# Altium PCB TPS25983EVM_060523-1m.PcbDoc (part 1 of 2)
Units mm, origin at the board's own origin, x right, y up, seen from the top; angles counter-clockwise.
Board outline 76.2 x 78.74 mm, 4 copper layers (L1-Top Layer, L2-GND1, L3-PWR/SIG, L4-Bottom Layer), stack 1.554 mm thick; 100 components, 38 nets, 213 pads, 280 vias.
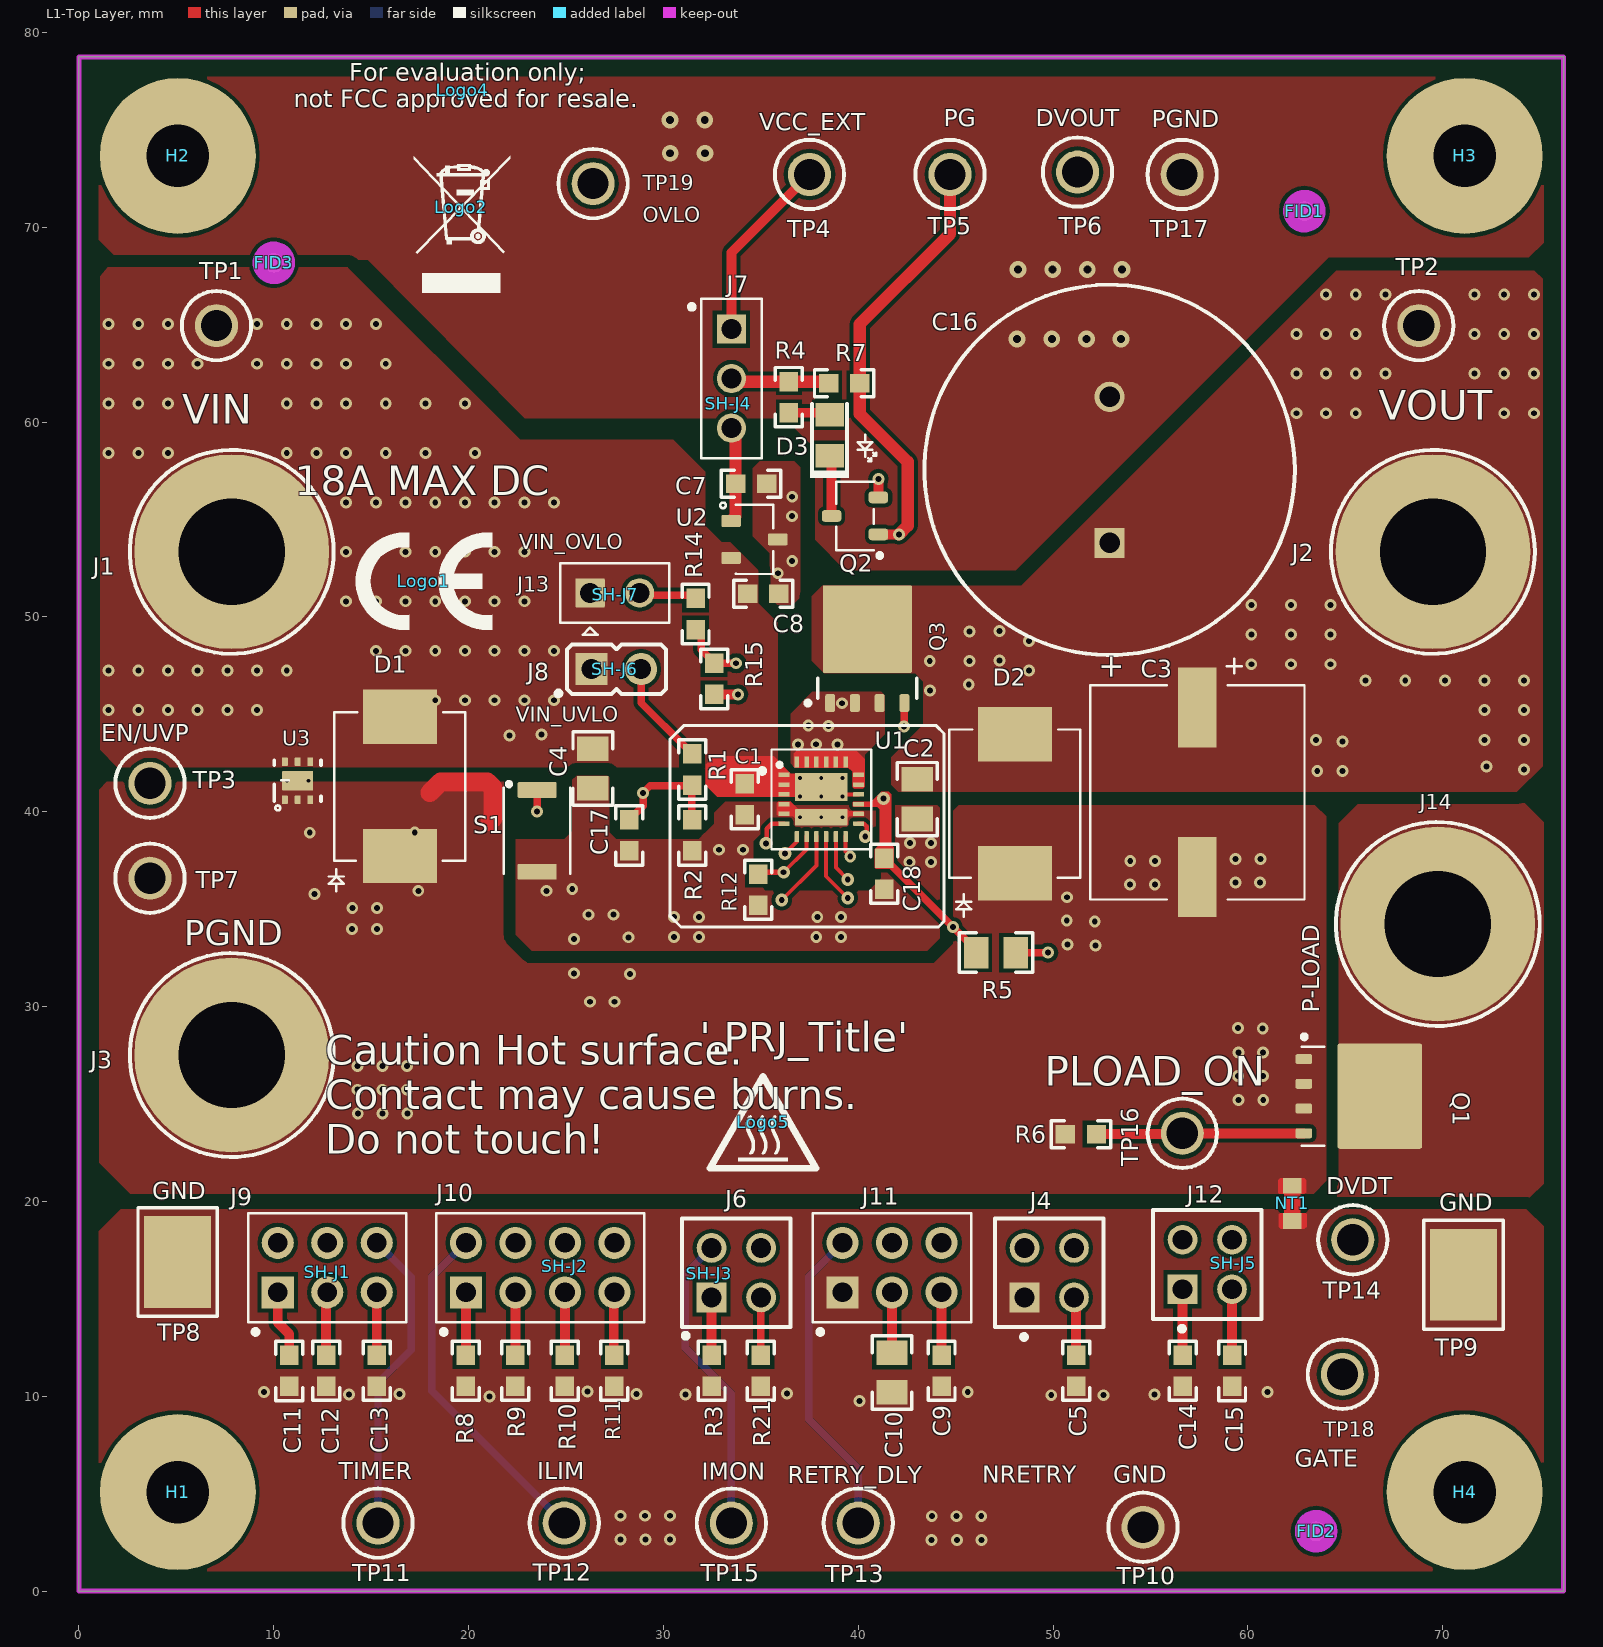
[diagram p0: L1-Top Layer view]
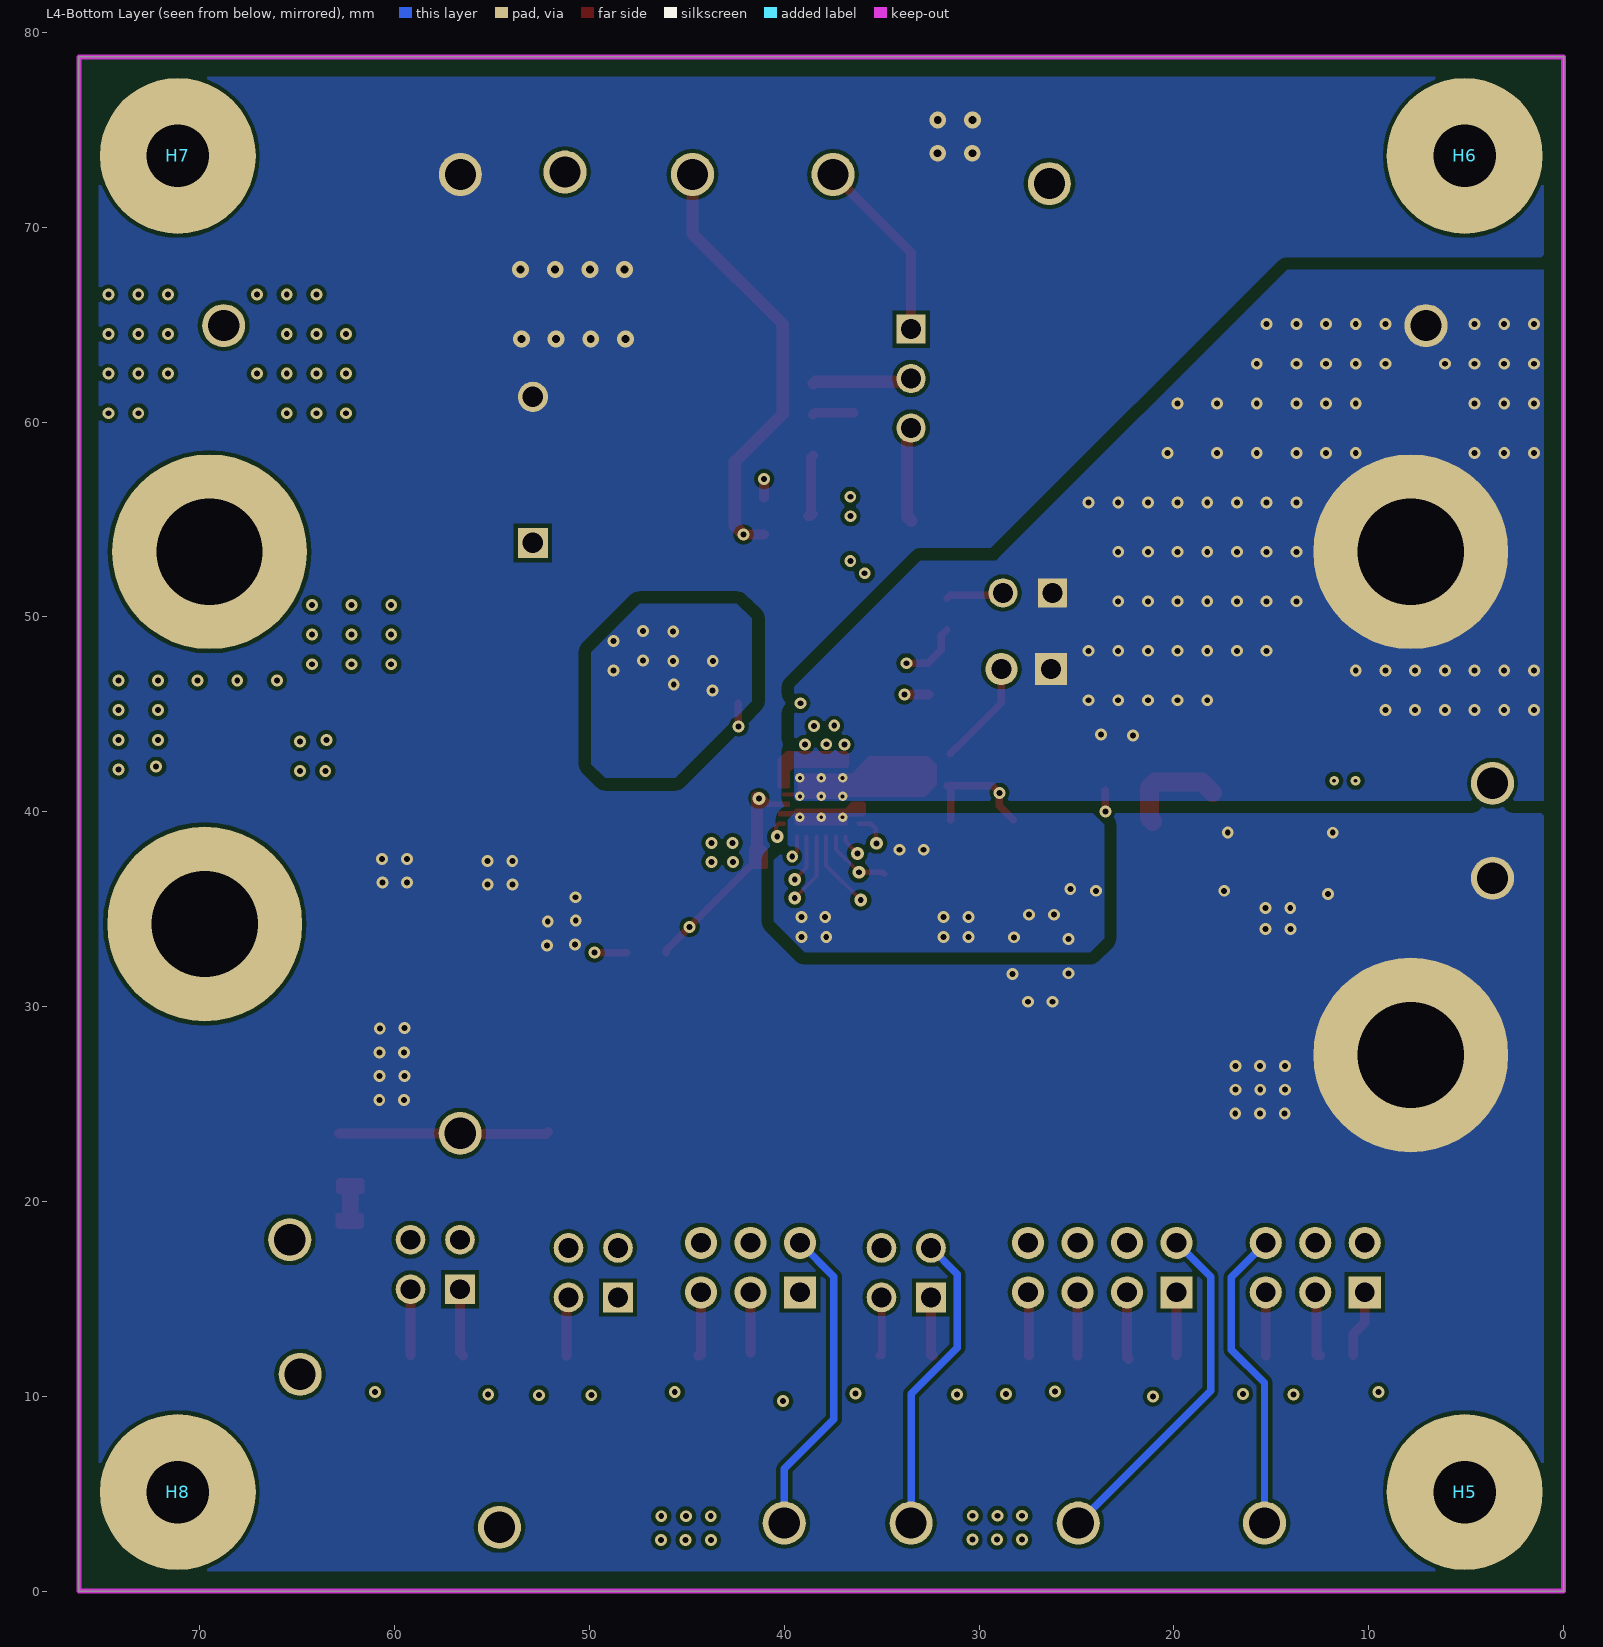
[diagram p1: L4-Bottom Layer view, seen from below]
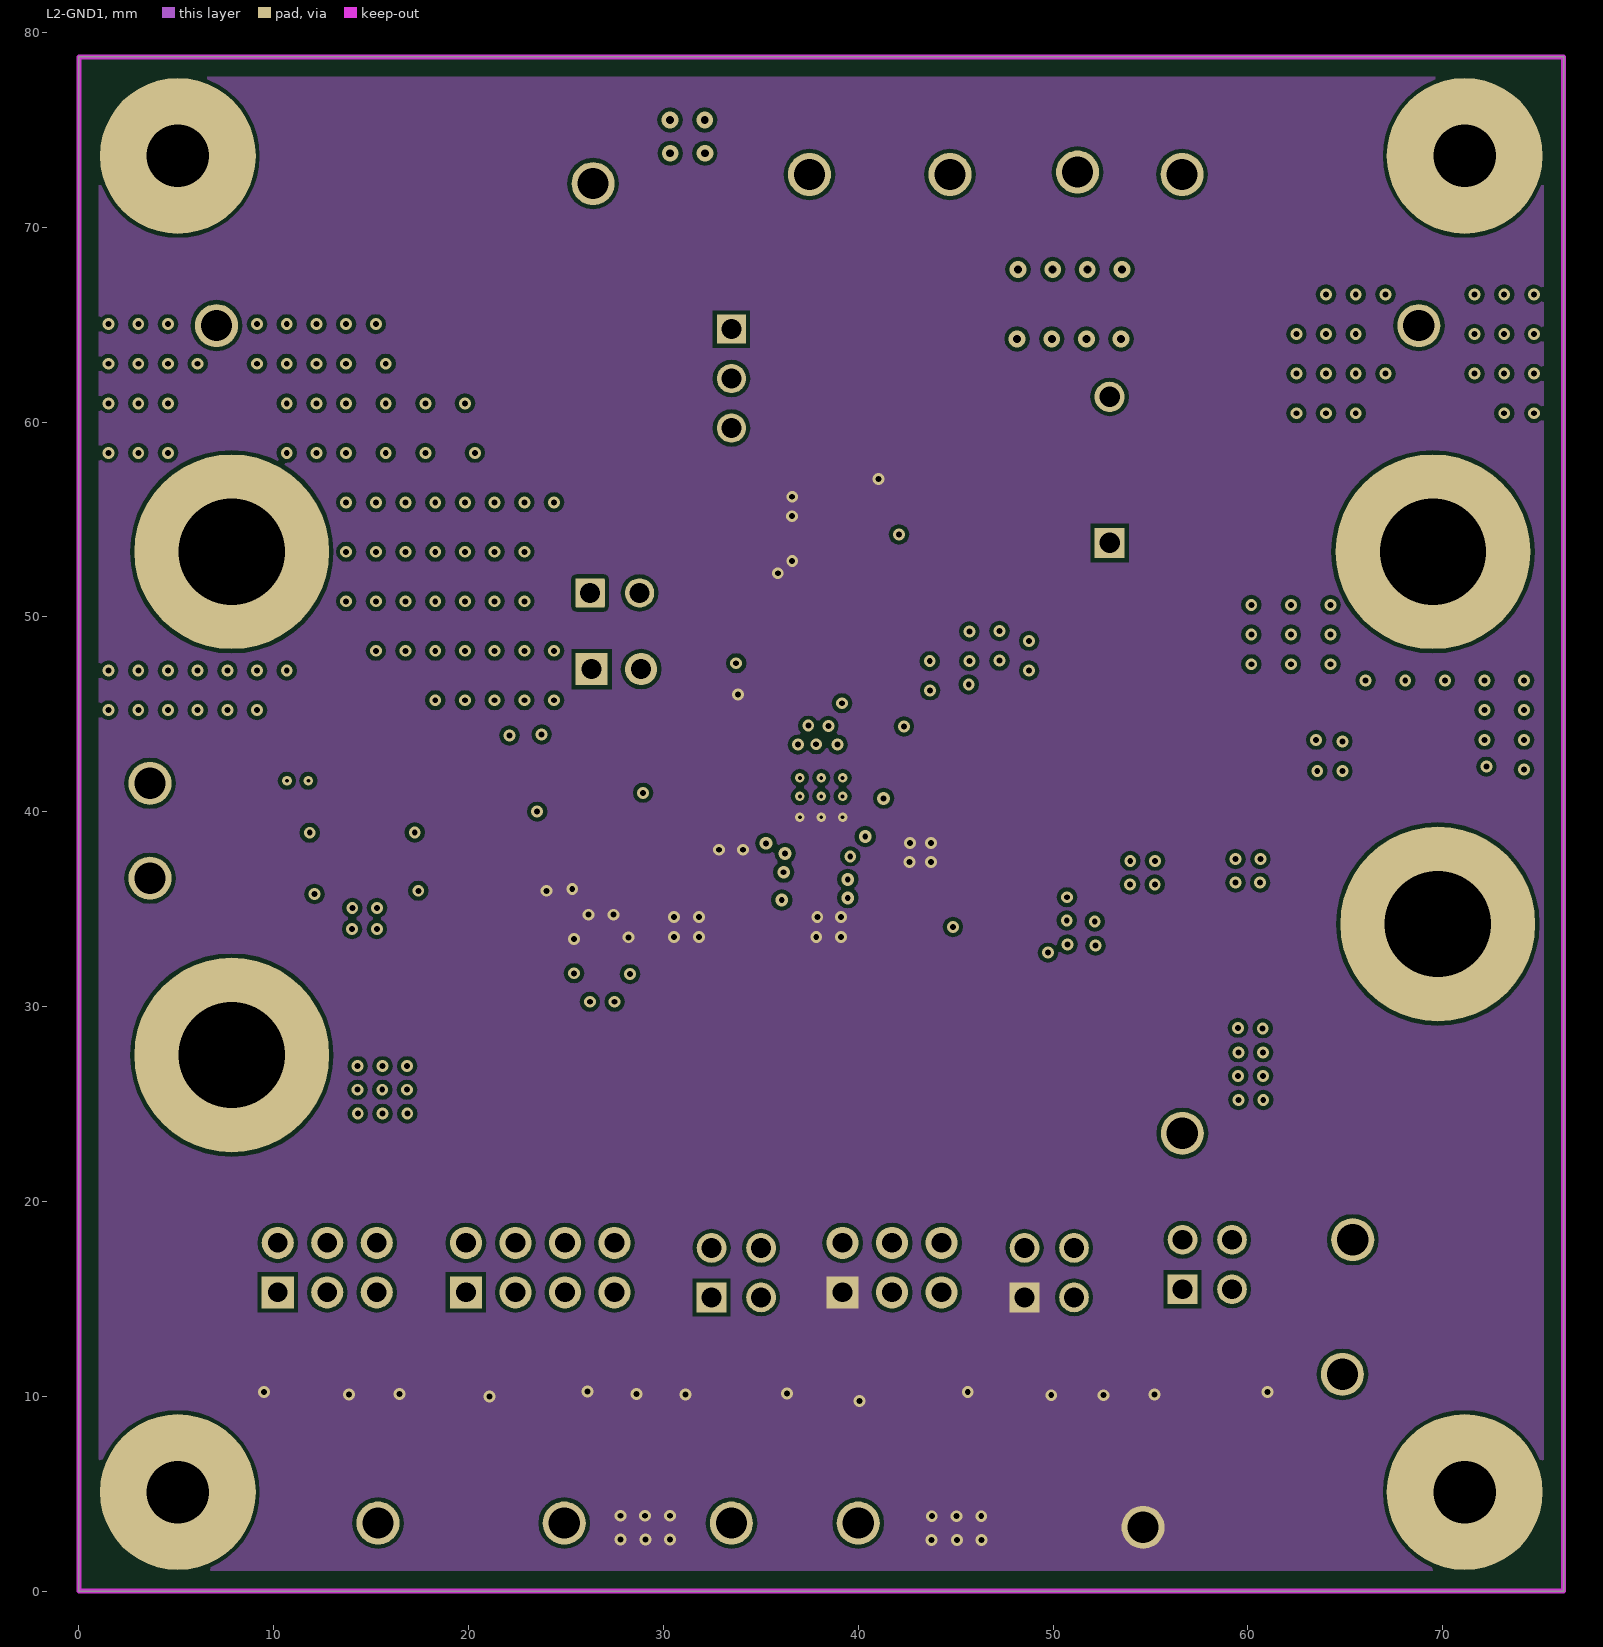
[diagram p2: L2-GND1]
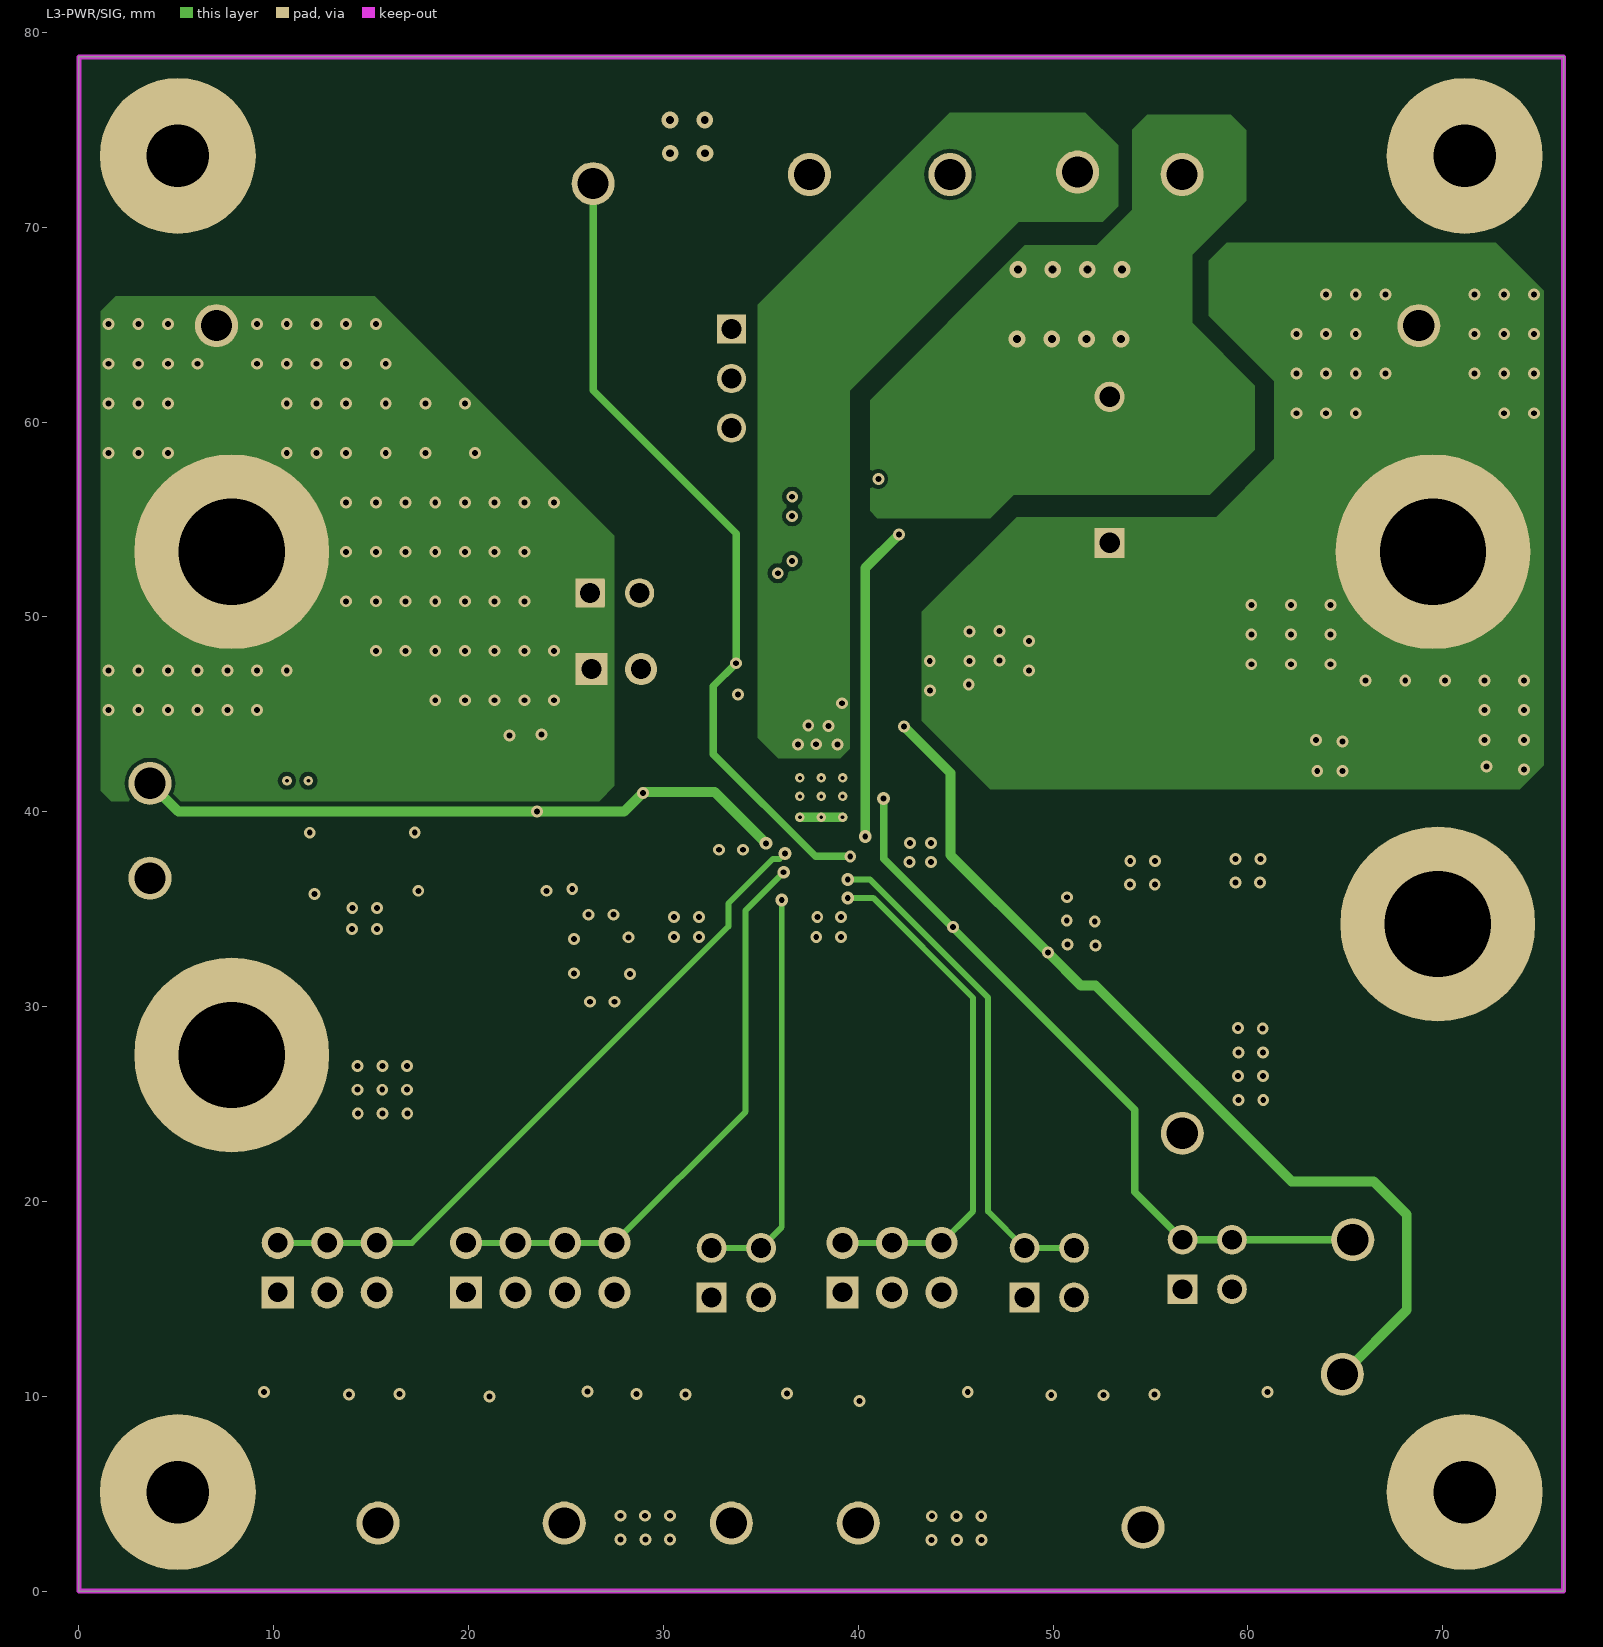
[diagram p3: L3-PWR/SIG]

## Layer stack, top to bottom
Top Solder: solder mask 0.0102, Solder Resist, Dk 3.5
L1-Top Layer: signal copper 0.0711
Dielectric 3: prepreg 0.4064, FR-4 High Tg, Dk 4.2
L2-GND1: signal copper 0.0711
Dielectric 2: prepreg 0.4572, FR-4 High Tg, Dk 4.2
L3-PWR/SIG: signal copper 0.0711
Dielectric1: prepreg 0.4064, FR-4 High Tg, Dk 4.2
L4-Bottom Layer: signal copper 0.0711
Bottom Solder: solder mask 0.0102, Solder Resist, Dk 3.5

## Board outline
0,0 0,78.74 76.2,78.74 76.2,0

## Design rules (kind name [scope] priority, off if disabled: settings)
AcuteAngle [All] p1: minimum=4.50000000000000E+0001 checktracksonly=FALSE
AssemblyTestPointUsage [All] p1: valid=2
BoardOutlineClearance [All] p1: gap=1.016 ignorepadtopadclearanceinfootprint=FALSE except(0: Text-OutlineEdge Text-CavityEdge Text-CutoutEdge Text-SplitBarrior Text-SplitContinuation)
Clearance Clearance_Fiducialmark [IsKeepOut and InComponentClass('FiducialMark') vs IsPad and InComponentClass('FiducialMark')] p1: gap=0 ignorepadtopadclearanceinfootprint=FALSE
Clearance Clearance_Keepouts [((IsTrack Or IsArc) And Not InPoly) And IsFree and IsKeepOut vs ((IsTrack Or IsArc) And Not InPoly) And IsFree and IsKeepOut] p2: gap=0 ignorepadtopadclearanceinfootprint=FALSE
Clearance "banana jack" [InPadClass('banan jack')] p3: gap=0.635 ignorepadtopadclearanceinfootprint=FALSE except(0: Arc-Hole Track-Hole SMDPad-Hole THPad-Hole Via-Hole Fill-Hole Poly-Hole Region-Hole Text-Hole)
Clearance MOUNTING_HOLE_CLEARENCE [InPadClass('MOUNTING')] p4: gap=0.635 ignorepadtopadclearanceinfootprint=FALSE except(0: Arc-Hole Track-Hole SMDPad-Hole THPad-Hole Via-Hole Fill-Hole Poly-Hole Region-Hole Text-Hole)
Clearance U1 [InComponent('U1')] p5: gap=0.198 ignorepadtopadclearanceinfootprint=FALSE except(0: Arc-Hole Track-Hole SMDPad-Hole THPad-Hole Via-Hole Fill-Hole Poly-Hole Region-Hole Text-Hole)
Clearance [All] p6: gap=0.203 ignorepadtopadclearanceinfootprint=FALSE except(0: Arc-Hole Track-Hole SMDPad-Hole THPad-Hole Via-Hole Fill-Hole Poly-Hole Region-Hole Text-Hole; 0.249: SMDPad-SMDPad; 0.254: THPad-THPad Via-Via; 0.305: Fill-Fill Fill-Poly; 0.635: Poly-Poly)
Clearance Clearance_Poly [InPolygon] p7: gap=0.635 ignorepadtopadclearanceinfootprint=FALSE except(0: Arc-Hole Track-Hole SMDPad-Hole THPad-Hole Via-Hole Fill-Hole Poly-Hole Region-Hole Text-Hole)
ComponentClearance ComponentClearance_MountingHoles_FiducialMarks [InComponentClass('Mounting Holes') vs InComponentClass('FiducialMark')] p1: gap=1.27 collisioncheckmode=3 verticalgap=0.254 showdistances=FALSE
ComponentClearance ComponentClearance_Shunt [InComponentClass('Header') vs InComponentClass('Shunt')] p2: gap=0 collisioncheckmode=3 verticalgap=0 showdistances=FALSE
ComponentClearance ComponentClearance_Logo [InComponentClass('Logo')] p3: gap=1.016 collisioncheckmode=3 verticalgap=0.254 showdistances=FALSE
ComponentClearance ComponentClearance_ScrewToNut [(HasFootprint('NY PMS 440 0025 PH')) vs (HasFootprint('Keystone_1902C'))] p4: gap=0.127 collisioncheckmode=3 verticalgap=0.254 showdistances=FALSE
ComponentClearance ComponentClearance_MountingHoles [InComponentClass('Mounting Holes')] p5: gap=2.54 collisioncheckmode=3 verticalgap=2540 showdistances=FALSE
ComponentClearance ComponentClearance_SmallPassives [HasFootprint('0201*') or HasFootprint('0402*') or HasFootprint('0508') or HasFootprint('0603*') or HasFootprint('0612') or HasFootprint('0805*') or HasFootprint('0815*') or HasFootprint('0830*') or HasFootprint('1206*') or HasFootprint('1210*') or HasFootprint('1808*') or HasFootprint('1812*') or HasFootprint('1825*') or HasFootprint('2010*') or HasFootprint('2220*') or HasFootprint('2225*') or HasFootprint('2512*') or HasFootprint('2728*') or HasFootprint('3518*') vs HasFootprint('0201*') or HasFootprint('0402*') or HasFootprint('0508') or HasFootprint('0603*') or HasFootprint('0612') or HasFootprint('0805*') or HasFootprint('0815*') or HasFootprint('0830*') or HasFootprint('1206*') or HasFootprint('1210*') or HasFootprint('1808*') or HasFootprint('1812*') or HasFootprint('1825*') or HasFootprint('2010*') or HasFootprint('2220*') or HasFootprint('2225*') or HasFootprint('2512*') or HasFootprint('2728*') or HasFootprint('3518*')] p6: gap=0.38 collisioncheckmode=3 verticalgap=0.254 showdistances=FALSE
ComponentClearance ComponentClearance_THtoSMT [IsThruComponent vs IsSMTComponent] p7: gap=1.016 collisioncheckmode=3 verticalgap=0.762 showdistances=FALSE
ComponentClearance ComponentClearance_THtoTH [IsThruComponent vs IsThruComponent] p8: gap=0.762 collisioncheckmode=3 verticalgap=0.762 showdistances=FALSE
ComponentClearance [All] p9: gap=0.254 collisioncheckmode=3 verticalgap=0.254 showdistances=FALSE
DiffPairsRouting [All] p1: maxlimit=2.54 minlimit=0.254 mostfreqgap=0.254 toplayer_minwidth=0.381 toplayer_maxwidth=0.381 toplayer_prefwidth=0.381 midlayer1_minwidth=0.381 midlayer1_maxwidth=0.381 midlayer1_prefwidth=0.381 midlayer2_minwidth=0.381 midlayer2_maxwidth=0.381 midlayer2_prefwidth=0.381 bottomlayer_minwidth=0.381 bottomlayer_maxwidth=0.381 bottomlayer_prefwidth=0.381 maxuncoupledlength=25.4
FabricationTestPointUsage TestPointUsage [All] p1: valid=2 allowmultiple=FALSE
FabricationTestpoint Testpoint [All] p1: side=3 testpointundercomponent=TRUE minsize=1.016 maxsize=2.54 preferedsize=1.524 minholesize=0 maxholesize=1.016 preferedholesize=0.813 testpointgrid=0.025 allowsidetop=TRUE allowsidebottom=TRUE usegrid=TRUE gridtolerance=0
FanoutControl Fanout_LCC [IsLCC] p1: bgadir=Out bgaviamode=Centered fanoutstyle=Auto fanoutdirection=Alternating viagrid=0.025 // Fanout_LCC (Default Rule)
FanoutControl Fanout_BGA [IsBGA] p2: bgadir=Out bgaviamode=Centered fanoutstyle=Auto fanoutdirection=Alternating viagrid=0.025 // Fanout_BGA (Default Rule)
FanoutControl Fanout_Default [All] p4: bgadir=Out bgaviamode=Centered fanoutstyle=Auto fanoutdirection=Alternating viagrid=0.025 // Fanout_Default (Default Rule)
FanoutControl Fanout_Small [(CompPinCount < 5)] p5: bgadir=Out bgaviamode=Centered fanoutstyle=Auto fanoutdirection=OutThenIn viagrid=0.025 // Fanout_Small (Default Rule)
HoleSize [All] p1: absolutevalues=TRUE maxlimit=6.375 minlimit=0.2 maxpercent=80.000 minpercent=20.000
MinimumAnnularRing MinimumAnnularRing_ThermalPadVias [IsVia and InAnyComponent] p1: minimumring=0.15
MinimumAnnularRing [All] p2: minimumring=0.152
MinimumSolderMaskSliver MinimumSolderMaskSliver_Logo [InComponentClass('Logo') vs InComponentClass('Logo')] p1: minsoldermaskwidth=0.018
MinimumSolderMaskSliver [All] p2: minsoldermaskwidth=0.102
PlaneConnect [All] p1: planeconnectstyle=Relief reliefexpansion=0.254 reliefentries=4 reliefconductorwidth=0.254 reliefairgap=0.254
PolygonConnect [All] p1: connectstyle=Direct reliefconductorwidth=0.254 reliefentries=4 polygonreliefangle="90 Angle" airgapwidth=0.254
RoutingVias ThermalPadVias [IsVia and InAnyComponent] p1: holewidth=0.2 width=0.5 viastyle="Through Hole" minholewidth=0.2 minwidth=0.5 maxholewidth=0.33 maxwidth=0.6
RoutingVias [All] p2: holewidth=0.305 width=0.61 viastyle="Through Hole" minholewidth=0.2 minwidth=0.508 maxholewidth=1.016 maxwidth=1.651
SilkToBoardRegionClearance [Not ((IsComment or IsDesignator) And (Hide <> 'False')) and not InRegion(1000,500,4000,800)] p1:
SilkToSilkClearance SilkToSilkClearance_Pb-FreeLogo [(HasFootprint('Pb-Free_Overlay_Medium') OR HasFootprint('Pb-Free_Overlay_Small')) vs (HasFootprint('Pb-Free_Overlay_Medium') OR HasFootprint('Pb-Free_Overlay_Small'))] p1: silktosilkclearance=0
SilkToSilkClearance [All] p2: silktosilkclearance=0.076
SilkToSolderMaskClearance SilkToComponentPadClearance [(IsPad or IsFill or IsRegion) and InAnycomponent] p1: minsilkscreentomaskgap=0.076 clearancetoexposedcopper=TRUE
SilkToSolderMaskClearance "Silk to Solder Mask Opening" [All] p2: minsilkscreentomaskgap=0.076 clearancetoexposedcopper=FALSE
SolderMaskExpansion [All] p1: expansion=0.05 istentingtop=FALSE
Width [All] p1: maxlimit=2.54 minlimit=0.203 preferedwidth=0.254 checkconnectedcopper=TRUE
15 further rules are at their usual default settings.

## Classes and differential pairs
component class Shunt: SH-J1 SH-J2 SH-J3 SH-J4 SH-J5 SH-J6 SH-J7
component class TPS25983EVM: C1 C2 C3 C4 C5 C7 C8 C9 C10 C11 C12 C13 C14 C15 C16 C17 C18 D1 D2 D3 J1 J2 J3 J4 J6 J7 J8 J9 J10 J11 J12 J13 J14 NT1 Q1 Q2 Q3 R1 R2 R3 R4 R5 R6 R7 R8 R9 R10 R11 R12 R14 R15 R21 S1 TP1 TP2 TP3 TP4 TP5 TP6 TP7 TP8 TP9 TP10 TP11 TP12 TP13 TP14 TP15 TP16 TP17 TP18 TP19 U1 U2 U3
component class "Mounting Holes": H1 H2 H3 H4
component class Header: J4 J6 J7 J8 J9 J10 J11 J12 J13
component class AssemblyNote: ZZ1 ZZ2 ZZ3
component class FiducialMark: FID1 FID2 FID3
component class TPS25983EVM_Hardware: FID1 FID2 FID3 H1 H2 H3 H4 H5 H6 H7 H8 Logo1 Logo2 Logo4 Logo5 SH-J1 SH-J2 SH-J3 SH-J4 SH-J5 SH-J6 SH-J7 ZZ1 ZZ2 ZZ3

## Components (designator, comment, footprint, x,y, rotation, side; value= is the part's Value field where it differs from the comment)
C1 "C0603C103J5RACTU" 0603 34.163,40.64 r270 top value=0.01uF
C2 "GMK212B7105KG-T" 0805_HV 43.028,40.646 r270 top value=1uF
C3 "EEE-FC1V221P" SM_RADIAL_G 57.398,40.999 r270 top locked value=220uF
C4 "GMK212B7105KG-T" 0805_HV 26.374,42.219 r270 top value=1uF
C5 "885012206070" 0603 51.18,11.308 r270 top value=0.068uF
C7 "06035C104KAT2A" 0603 34.5,56.839 r0 top value=0.1uF
C8 "06035C104KAT2A" 0603 35.125,51.196 r0 top value=0.1uF
C9 "C0603C102K3GACTU" 0603 44.272,11.308 r270 top value=1000pF
C10 "GRM21B5C1H203JA01L" 0805_HV 41.732,11.216 r270 top value=0.02uF
C11 "06035A471JAT2A" 0603 10.795,11.303 r270 top value=470pF
C12 "C0603C472J5RACTU" 0603 12.685,11.308 r270 top value=4700pF
C13 "C1608X7S2A473K080AB" 0603 15.286,11.308 r270 top value=0.047uF
C14 "C0603X332K5RACTU" 0603 56.642,11.308 r270 top value=3300pF
C15 "GRM1885C1H103JA01D" 0603 59.182,11.303 r270 top value=0.01uF
C16 "UPW1V182MHD6" PW_1800X2000 52.9,57.543 r90 top locked value=1800uF
C17 "885012006057" 0603 28.245,38.786 r270 top value=100pF
C18 "C0603X332K5RACTU" 0603 41.326,36.817 r270 top value=3300pF
D1 "SMCJ13A-TR" SMC 16.473,41.296 r270 top value=13V
D2 "B530C-13-F" SMC 48.04,40.412 r270 top value=30V
D3 "LTST-C170KGKT" LTST-C170KGKT_GREEN 38.531,59.325 r270 top value=Green
FID1 "Fiducial" Fiducial10-20 62.898,70.823 r0 top
FID2 "Fiducial" Fiducial10-20 63.498,3.072 r0 top
FID3 "Fiducial" Fiducial10-20 10.008,68.174 r0 top
H1 "NY PMS 440 0025 PH" "NY PMS 440 0025 PH" 5.08,5.08 r0 top
H2 "NY PMS 440 0025 PH" "NY PMS 440 0025 PH" 5.08,73.66 r0 top
H3 "NY PMS 440 0025 PH" "NY PMS 440 0025 PH" 71.12,73.66 r0 top
H4 "NY PMS 440 0025 PH" "NY PMS 440 0025 PH" 71.12,5.08 r0 top
H5 "1902C" Keystone_1902C 5.08,5.08 r180 bottom
H6 "1902C" Keystone_1902C 5.08,73.66 r180 bottom
H7 "1902C" Keystone_1902C 71.12,73.66 r180 bottom
H8 "1902C" Keystone_1902C 71.12,5.08 r180 bottom
J1 "VIN" Keystone575-8 7.844,53.34 r90 top locked
J2 "VOUT" Keystone575-8 69.493,53.34 r90 top
J3 "PGND" Keystone575-8 7.844,27.509 r90 top
J4 "PEC02DAAN" Sullins_PEC02DAAN 49.803,16.342 r90 top
J6 "PEC02DAAN" Sullins_PEC02DAAN 33.739,16.342 r90 top
J7 "Header_3x1_Launchpad" CONN_PEC03SAAN 33.488,62.23 r270 top
J8 "Header_2x1" Sullins_PBC02SAAN 27.584,47.32 r90 top
J9 "PEC03DAAN" SULLINS_PEC03DAAN 12.746,16.604 r0 top
J10 "PEC04DAAN" CONN_PEC04DAAN 23.674,16.604 r0 top
J11 "PEC03DAAN" SULLINS_PEC03DAAN 41.732,16.604 r0 top
J12 "PEC02DAAN" Sullins_PEC02DAAN 57.912,16.764 r90 top
J13 "PEC02SAAN" CONN_PEC02SAAN 27.508,51.232 r0 top
J14 "P-LOAD" Keystone575-8 69.745,34.237 r90 top
Logo1 "CE Mark" CE_Mark_5mm 17.709,51.83 r0 top
Logo2 "WEEE logo" WEEE_Minimum 19.618,71.017 r0 top
Logo4 "FCC disclaimer" FCC_disclaimer_stacked 19.71,77.038 r0 top
Logo5 "CAUTION HOT SURFACE" IEC_HotSurface_Small 35.119,24.064 r0 top
NT1 "Net-Tie" NETTIE_0603 62.279,19.896 r90 top net-tie
Q1 "CSD17573Q5B" DNK0008A 65.685,25.4 r0 top value=30V
Q2 "2N7002" SOT-23 39.83,55.182 r180 top value=60V
Q3 "CSD18511Q5A" DQJ0008A 40.462,48.373 r90 top value=40V
R1 "RC0603FR-071ML" 0603 31.471,42.164 r90 top value=1.00Meg
R2 "CRCW0603124KFKEA" 0603 31.471,38.786 r90 top value=124k
R3 "RC0603FR-07511RL" 0603 32.469,11.308 r90 top value=511
R4 "RC0603FR-071KL" 0603 36.438,61.276 r270 top value=1.00k
R5 "CRCW08051R13FKEA" 0805_HV 47.066,32.766 r0 top value=1.13
R6 "RC0603FR-07470RL" 0603 51.426,23.454 r0 top value=470
R7 "RG1608P-103-B-T5" 0603 39.278,61.981 r180 top value=10.0k
R8 "RC0603FR-07768RL" 0603 19.864,11.308 r90 top value=768
R9 "RC0603FR-07300RL" 0603 22.404,11.308 r90 top value=300
R10 "RC0603FR-0782RL" 0603 24.944,11.308 r90 top value=82.0
R11 "RC0603FR-0773R2L" 0603 27.484,11.308 r90 top value=73.2
R12 "RT0603BRD07511RL" 0603 34.86,35.995 r270 top value=511
R14 "RC0603FR-071ML" 0603 31.648,50.147 r90 top value=1.00Meg
R15 "RC0603FR-0795K3L" 0603 32.603,46.82 r90 top value=95.3k
R21 "RC0603FR-071KL" 0603 35.001,11.308 r90 top value=1.00k
S1 "SKRKAEE020" SW_SKRKAE 23.52,39.014 r270 top
SH-J1 "SNT-100-BK-G" SNT-100-BK-G 12.746,16.371 r90 top value=1x2
SH-J2 "SNT-100-BK-G" SNT-100-BK-G 24.943,16.662 r90 top value=1x2
SH-J3 "SNT-100-BK-G" SNT-100-BK-G 32.346,16.29 r90 top value=1x2
SH-J4 "SNT-100-BK-G" SNT-100-BK-G 33.315,60.937 r90 top value=1x2
SH-J5 "SNT-100-BK-G" SNT-100-BK-G 59.252,16.82 r90 top value=1x2
SH-J6 "SNT-100-BK-G" SNT-100-BK-G 27.508,47.32 r180 top value=1x2
SH-J7 "SNT-100-BK-G" SNT-100-BK-G 27.536,51.147 r180 top value=1x2
TP1 "VIN" Keystone5010 7.063,64.949 r0 top
TP2 "VOUT" Keystone5010 68.77,64.949 r0 top
TP3 "EN/UVP" Keystone5012 3.647,41.46 r0 top
TP4 "VCC_EXT" Keystone5013 37.493,72.707 r0 top
TP5 "PG" Keystone5012 44.707,72.707 r0 top
TP6 "DVOUT" Keystone5010 51.255,72.829 r0 top
TP7 "PGND" Keystone5011 3.647,36.587 r0 top
TP8 "GND" Testpoint_Keystone_Compact 5.065,16.889 r270 top
TP9 "GND" Testpoint_Keystone_Compact 71.061,16.242 r90 top
TP10 "GND" Keystone5011 54.617,3.275 r0 top
TP11 "ITIMER" Keystone5012 15.352,3.49 r0 top
TP12 "ILIM" Keystone5012 24.909,3.49 r0 top
TP13 "RETRY_DLY" Keystone5012 39.999,3.49 r0 top
TP14 "DVDT" Keystone5012 65.38,18.034 r0 top
TP15 "IMON" Keystone5012 33.488,3.49 r0 top
TP16 "LOAD_ON" Keystone5013 56.632,23.495 r0 top
TP17 "PGND" Keystone5011 56.621,72.707 r0 top
TP18 "GATE" Keystone5012 64.846,11.125 r0 top
TP19 "OVLO" Keystone5012 26.391,72.238 r0 top
U1 "TPS25983xyNRGE" RGE0024M-MFG 38.1,40.64 r0 top
U2 "LM3480IM3-3.3/NOPB" DBZ0003A_N 34.671,53.975 r0 top
U3 "TVS2200DRVR" DRV0006A 11.226,41.591 r90 top
ZZ1 "These assemblies are ESD sensitive, ESD precautions shall be observed." AssemblyNote -0.874,90.501 r0 top
ZZ2 "These assemblies must be clean and free from flux and all contaminants. Use of no clean flux is not acceptable." AssemblyNote -0.874,88.251 r0 top
ZZ3 "These assemblies must comply with workmanship standards IPC-A-610 Class 2, unless otherwise specified." AssemblyNote -0.874,86.002 r0 top

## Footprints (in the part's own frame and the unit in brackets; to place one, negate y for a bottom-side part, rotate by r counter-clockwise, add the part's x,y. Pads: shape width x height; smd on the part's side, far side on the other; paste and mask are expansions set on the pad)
0603 [mm] "0603 from SM-752 data"
  rect 1x0.95 smd: 1(-0.8,0) 2(0.8,0)
  silkscreen extent -1.52,-0.69 1.52,0.69, body extent -0.87,-0.47 0.87,0.47, height 1
0805_HV [mil] "0805 with 30mil clearance between pads"
  rect 50x63 smd: 1(-40,0) 2(40,0)
  silkscreen extent -74,-40 74,40, body extent -43,-29 43,29, height 57
AssemblyNote [mm] "Assembly Note"
CE_Mark_5mm [mm] "Minimum text height for CE Mark"
  silkscreen extent -3.5,-2.5 3.5,2.5
CONN_PEC02SAAN [mm] "SULLINS"
  rrect7% 1.5x1.5 hole 1.016 mask+0.05: 1(-1.27,0)
  round 1.5 hole 1.016 mask+0.05: 2(1.27,0)
  silkscreen extent -2.79,-2.16 2.79,1.52, body extent -2.54,-1.27 2.54,1.27, height 8.38
CONN_PEC03SAAN [mm] "SULLINS"
  rect 1.5x1.5 hole 1.016 mask+0.05: 1(-2.54,0)
  round 1.5 hole 1.016 mask+0.05: 2(0,0) 3(2.54,0)
  silkscreen extent -4.09,-2.13 4.09,1.55, body extent -3.84,-1.3 3.84,1.3, height 8.38
CONN_PEC04DAAN [mm] "SULLINS"
  rect 1.65x1.65 hole 1.016 mask+0: 1(-3.81,-1.27)
  round 1.65 hole 1.016 mask+0: 2(-3.81,1.27) 3(-1.27,-1.27) 4(-1.27,1.27) 5(1.27,-1.27) 6(1.27,1.27) 7(3.81,-1.27) 8(3.81,1.27)
  silkscreen extent -5.33,-3.4 5.33,2.79, body extent -5.08,-2.54 5.08,2.54, height 8.38
DBZ0003A_N [mm] "SOT23, 3-Leads, Body 2.9x1.3mm, Pitch 0.95mm, Lead Span 2.4mm, IPC Medium Density"
  rrect17% 1x0.6 smd mask+0.05: 1(-1.2,0.95) 2(-1.2,-0.95) 3(1.2,0)
  silkscreen extent -1.75,-1.77 0.95,1.89, body extent -1.26,-1.46 1.26,1.46, height 0.98
DNK0008A [mm] "SON, 8-Leads, Body 5x6mm"
  rrect39% 0.86x0.51 smd paste+0 mask+0.038: 1(-2.82,1.905) 2(-2.82,0.635) 3(-2.82,-0.635) 4(-2.82,-1.905) 5(2.82,-1.905) 6(2.82,-0.635) 7(2.82,0.635) 8(2.82,1.905)
  rrect5% 4.34x5.4 smd paste+0 mask+0.038: 9(1.08,0)
  silkscreen extent -2.92,-2.54 -1.78,3.15, body extent -3.05,-2.55 3.05,2.55, height 1.06
DQJ0008A [mm] "SMD, 8-Leads, Body 5.75x4.9mm"
  rrect39% 0.91x0.51 smd paste+0 mask+0.038: 1(-2.795,1.905) 2(-2.795,0.635) 3(-2.795,-0.635) 4(-2.795,-1.905) 5(2.795,-1.905) 6(2.795,-0.635) 7(2.795,0.635) 8(2.795,1.905)
  rrect2% 4.49x4.57 smd paste+0 mask+0.038: 9(1.005,0)
  silkscreen extent -2.9,-2.54 -1.54,3.15, body extent -3.13,-2.45 3.13,2.45, height 1.15
DRV0006A [mm] "SON, 6-Leads, Body 2x2mm, Pitch 0.65mm, Thermal Pad 1.6x1mm, TI Recommended"
  rrect33% 0.45x0.3 smd mask+0.05: 1(-0.975,0.65) 2(-0.975,0) 3(-0.975,-0.65) 4(0.975,-0.65) 5(0.975,0) 6(0.975,0.65)
  rrect50% 1x0.7 on Top Paste mask+0.05: 7(0,0.45) 7(0,-0.45)
  rrect10% 1x1.6 smd paste-0.5 mask+0.05: 7(0,0)
  silkscreen extent -1.52,-1.2 1.05,1.2, body extent -1.05,-1.05 1.05,1.05, height 0.81
FCC_disclaimer_stacked [mm]
Fiducial10-20 [mm]
  round 1 smd mask+0.5: 1(0,0)
  L1-Top Layer keep-out circle w1.178: c0,0 r0.5
IEC_HotSurface_Small [mm]
  silkscreen extent -2.72,-2.36 2.72,2.35
Keystone575-8 [mm] "Banana Jack"
  round 10 hole 5.45: 1(0,0)
  silkscreen extent -5.23,-5.23 5.23,5.23, body extent -3.92,-3.94 3.95,3.94, height 2.36
Keystone5010 [mil] "Keystone Multipurpose loops"
  round 87 hole 63: 1(0,0)
  silkscreen extent -70,-70 70,70, body extent -63,-63 63,62, height 319
Keystone5011 [mil] "Keystone Multipurpose loops"
  round 87 hole 63: 1(0,0)
  silkscreen extent -70,-70 70,70, body extent -63,-63 63,62, height 319
Keystone5012 [mil] "Keystone Multipurpose loops"
  round 87 hole 63: 1(0,0)
  silkscreen extent -70,-70 70,70, body extent -63,-63 63,62, height 319
Keystone5013 [mil] "Keystone Multipurpose loops"
  round 87 hole 63: 1(0,0)
  silkscreen extent -70,-70 70,70, body extent -63,-63 63,62, height 319
Keystone_1902C [mil] "Hex Standoff, 4-40 threaded, nylon"
  round 1 on Mech4: 0(0,0)
  body extent -145,-126 146,126, height 501
LTST-C170KGKT_GREEN [mm] "LITE-ON"
  rect 1.2x1.454 smd mask+0.05: 1(-1.05,0) 2(1.05,0)
  silkscreen extent -1.6,-1 2.2,1, body extent -1.05,-0.67 1.05,0.67, height 1.1
NETTIE_0603 [mm] "Net Tie 0603 size"
  rect 0.8x0.95 smd paste-1 mask-2.54: 1(-0.9,0) 2(0.9,0)
  L1-Top Layer region: -0.6,0.406 0.6,0.406 0.6,-0.406 -0.6,-0.406
"NY PMS 440 0025 PH" [mm] "4-40 nylon screw and mounting hole"
  round 8 hole 3.2 unplated: 1(0,0)
  body extent -3.31,-3.3 3.3,3.3, height 2.69
PW_1800X2000 [mm] "TH, 2-Leads, Dia 18mm, Pin Spacing 7.5mm"
  rect 1.55x1.55 hole 1.05 mask+0.05: 1(-3.75,0)
  round 1.55 hole 1.05 mask+0.05: 2(3.75,0)
  silkscreen extent -9.5,-9.5 9.5,9.5, body extent -9.18,-9.23 9.22,9.24, height 22.01
RGE0024M-MFG [mm]
  rrect42% 0.575x0.24 smd paste+0 mask+0: 1(-1.913,1.25) 2(-1.913,0.75) 3(-1.913,0.25) 4(-1.913,-0.25) 5(-1.913,-0.75) 6(-1.913,-1.25) 13(1.913,-1.25) 14(1.913,-0.75) 15(1.913,-0.25) 16(1.913,0.25) 17(1.913,0.75) 18(1.913,1.25)
  rrect42% 0.24x0.575 smd paste+0 mask+0: 7(-1.25,-1.913) 8(-0.75,-1.913) 9(-0.25,-1.913) 10(0.25,-1.913) 11(0.75,-1.913) 12(1.25,-1.913) 19(1.25,1.913) 20(0.75,1.913) 21(0.25,1.913) 22(-0.25,1.913) 23(-0.75,1.913) 24(-1.25,1.913)
  rrect7% 2.7x1.45 smd paste-1000 mask+0: 25(0,0.625)
  rrect12% 2.7x0.85 smd paste-1000 mask+0: 26(0,-0.925)
  silkscreen extent -3.15,-2.55 2.55,2.55, body extent -2.3,-2.3 2.3,2.3, height 0.25
SM_RADIAL_G [mm] "10 x 10.2mm:  Panasonic G"
  rect 4.1x2 smd mask+0.05: 1(-4.35,0) 2(4.35,0)
  silkscreen extent -6.86,-5.5 5.5,5.5, body extent -5.25,-5.25 5.25,5.25, height 10.5
SMC [mil] "Molded Diode, 2-Leads, Body 6.9x5.8mm, IPC Medium Density, based on OnSemi component dimensions and land patterns"
  rect 110x150 smd mask+1.97: 1(-140.49,0) 2(140.49,0)
  silkscreen extent -150,-132 150,132, body extent -156,-116 156,116, height 91
SNT-100-BK-G [mil] "Samtec STEP model"
  round 1 on Mech3: 0(0,0)
  body extent -100,-50 100,50, height 344
SOT-23 [mm] "SOT23, 3-Leads, Body 2.9x1.3mm, Pitch 0.95mm, Lead Span 2.5mm, IPC Medium Density"
  rrect50% 1x0.6 smd mask+0.05: 1(-1.2,0.95) 2(-1.2,-0.95) 3(1.2,0)
  silkscreen extent -1.37,-1.75 0.95,2.13, body extent -1.16,-1.45 1.21,1.45, height 1
Sullins_PBC02SAAN [mm] "Sullins 100mil, 1x2, 230 mil above insulator"
  rect 1.65x1.65 hole 1.016: 1(0,1.27)
  round 1.65 hole 1.016: 2(0,-1.27)
  silkscreen extent -1.37,-2.54 1.27,3.1, body extent -1.27,-2.54 1.27,2.54, height 8.38
Sullins_PEC02DAAN [mil] "Sullins Connector Solutions"
  rect 60x60 hole 40: 1(-50,50)
  round 60 hole 40: 2(50,50) 3(-50,-50) 4(50,-50)
  silkscreen extent -134,-110 110,110, body extent -110,-110 110,110, height 310
SULLINS_PEC03DAAN [mm] "SULLINS"
  rect 1.65x1.65 hole 1.016 mask+0: 1(-2.54,-1.27)
  round 1.65 hole 1.016 mask+0: 2(-2.54,1.27) 3(0,-1.27) 4(0,1.27) 5(2.54,-1.27) 6(2.54,1.27)
  silkscreen extent -4.06,-3.4 4.06,2.79, body extent -3.81,-2.54 3.81,2.54, height 8.38
SW_SKRKAE [mm] "SMD, 2-Leads, Body 3.9x2.9mm"
  rrect12% 0.8x2 smd mask+0.05: 1(-2.1,0) 2(2.1,0)
  silkscreen extent -2.2,-1.7 2.2,1.7, body extent -2.4,-1.45 2.4,1.45, height 2
Testpoint_Keystone_Compact [mil] "Compact SMT test point"
  rect 185x135 smd: 1(0,0)
  silkscreen extent -110,-80 110,80, body extent -75,-56 75,56, height 91
WEEE_Minimum [mm] "WEEElie bin"
  silkscreen extent -2.42,-4.38 2.52,2.65

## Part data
C1: library part CMP-0006850-4, "CAP, CERM, 0.01 uF, 50 V, +/- 5%, X7R, 0603", Cap_Case=0603, Manufacturer=Kemet, Supplier Part Number 1=399-1092-1-ND, TempCo=X7R, Tolerance_%=5%, Value1=Unknown, Value2=50V, ValueDisplayed=0.01uF
C2 C4: library part CMP-0008024-2, "CAP, CERM, 1 uF, 35 V, +/- 10%, X7R, 0805", Cap_Case=0805, Manufacturer="Taiyo Yuden", Supplier Part Number 1=587-1438-1-ND, TempCo=X7R, Tolerance_%=10%, Value1=Unknown, Value2=35V, ValueDisplayed=1uF
C3: library part CMP-0010667-1, "CAP, AL, 220 uF, 35 V, +/- 20%, 0.15 ohm, SMD", Cap_Case=G, Manufacturer=Panasonic, Supplier Part Number 1=PCE4026CT-ND, Tolerance_%=20%, Value1="0.15 ohm", Value2=35V, ValueDisplayed=220uF
C5: library part CMP-0750069-1, "CAP, CERM, 0.068 µF, 25 V,+/- 10%, X7R, 0603", Cap_Case=0603, Manufacturer="Wurth Elektronik", TempCo=X7R, Tolerance_%=10%, Value2=25V, ValueDisplayed=0.068µF
C7 C8: library part CMP-0006802-4, "CAP, CERM, 0.1 uF, 50 V, +/- 10%, X7R, 0603", Cap_Case=0603, Manufacturer=AVX, Supplier Part Number 1=478-5052-1-ND, TempCo=X7R, Tolerance_%=10%, Value1=Unknown, Value2=50V, ValueDisplayed=0.1uF
C9: library part CMP-0006846-4, "CAP, CERM, 1000 pF, 25 V, +/- 10%, C0G/NP0, 0603", Cap_Case=0603, Manufacturer=Kemet, Supplier Part Number 1=399-7833-1-ND, TempCo=C0G/NP0, Tolerance_%=10%, Value1="0 ohm", Value2=25V, ValueDisplayed=1000pF
C10: library part CMP-0080095-1, "CAP, CERM, 0.02 µF, 50 V,+/- 5%, C0G/NP0, 0805", Cap_Case=0805, Manufacturer=MuRata, Supplier Part Number 1=490-8307-1-ND, TempCo=C0G/NP0, Tolerance_%=5%, Value2=50V, ValueDisplayed=0.02µF
C11: library part CMP-0006790-4, "CAP, CERM, 470 pF, 50 V, +/- 5%, C0G/NP0, 0603", Cap_Case=0603, Manufacturer=AVX, Supplier Part Number 1=478-1183-1-ND, TempCo=C0G/NP0, Tolerance_%=5%, Value1="0.063 ohm", Value2=50V, ValueDisplayed=470pF
C12: library part CMP-0006942-4, "CAP, CERM, 4700 pF, 50 V, +/- 5%, X7R, 0603", Cap_Case=0603, Manufacturer=Kemet, Supplier Part Number 1=399-1088-1-ND, TempCo=X7R, Tolerance_%=5%, Value1=Unknown, Value2=50V, ValueDisplayed=4700pF
C13: library part CMP-0007060-4, "CAP, CERM, 0.047 uF, 100 V, +/- 10%, X7S, 0603", Cap_Case=0603, Manufacturer=TDK, Supplier Part Number 1=445-6032-1-ND, TempCo=X7S, Tolerance_%=10%, Value1="0.089796 ohm", Value2=100V, ValueDisplayed=0.047uF
C14 C18: library part CMP-0006985-4, "CAP, CERM, 3300 pF, 50 V, +/- 10%, X7R, 0603", Cap_Case=0603, Manufacturer=Kemet, Supplier Part Number 1=399-5339-1-ND, TempCo=X7R, Tolerance_%=10%, Value1=Unknown, Value2=50V, ValueDisplayed=3300pF
C15: library part CMP-0007174-4, "CAP, CERM, 0.01 uF, 50 V, +/- 5%, C0G/NP0, 0603", Cap_Case=0603, Manufacturer=MuRata, Supplier Part Number 1=490-9666-1-ND, TempCo=C0G/NP0, Tolerance_%=5%, Value1=Unknown, Value2=50V, ValueDisplayed=0.01uF
C16: library part CMP-0010552-2, "CAP, AL, 1800 uF, 35 V, +/- 20%, 0.028 ohm, TH", Cap_Case=18x20mm, Manufacturer=Nichicon, Supplier Part Number 1=493-1878-ND, Tolerance_%=20%, Value1="0.028 ohm", Value2=35V, ValueDisplayed=1800uF
C17: library part CMP-0006822-4, "CAP, CERM, 100 pF, 50 V, +/- 5%, C0G/NP0, 0603", Cap_Case=0603, Manufacturer="Wurth Elektronik", TempCo=C0G/NP0, Tolerance_%=5%, Value1=Unknown, Value2=50V, ValueDisplayed=100pF
D1: library part CMP-0085423-1, "Diode, TVS, Uni, 13 V, 21.5 Vc, 1500 W, 73 A, SMC", Manufacturer=STMicroelectronics, Value1=21.5V
D2: library part CMP-0028430-1, "Diode, Schottky, 30 V, 5 A, SMC", Manufacturer="Diodes Inc.", Supplier Part Number 1=B530C-FDICT-ND, Value1=5A, Value2=0.55V
D3: library part CMP-0002888-1, "LED, Green, SMD", Color=Green, Manufacturer=Lite-On, Supplier Part Number 1=160-1414-1-ND, Value1=W, Value2=2V
FID1 FID2 FID3: library part CMP-0077181-1, "Fiducial mark.  There is nothing to buy or mount.", Manufacturer=N/A
H1 H2 H3 H4: library part CMP-0003617-1, "Machine Screw, Round, #4-40 x 1/4, Nylon, Philips panhead", Manufacturer="B&F Fastener Supply", Supplier Part Number 1=H542-ND
H5 H6 H7 H8: library part CMP-0003610-1, Manufacturer=Keystone, Supplier Part Number 1=36-1902C-ND
J1 J2 J3 J14: library part CMP-0055166-2, "Standard Banana Jack, Uninsulated, 8.9mm", Manufacturer=Keystone, PartNumber=575-8, Supplier Part Number 1=36-575-8-ND
J4 J6 J12: library part CMP-0054558-1, "Header, 100mil, 2x2, Tin, TH", Manufacturer="Sullins Connector Solutions", Supplier Part Number 1=S2012E-02-ND
J7: library part CMP-0002338-1, "Header, 100mil, 3x1, Tin, TH", Color=Black, Current_A=3A, Manufacturer="Sullins Connector Solutions", PartNumber=PEC03SAAN, Supplier Part Number 1=S1012E-03-ND, Voltage_V=1.8kV
J8: library part CMP-0054566-1, "Header, 100mil, 2x1, Gold, TH", Color=Black, Current_A=3A, Manufacturer="Sullins Connector Solutions", PartNumber=PBC02SAAN, Supplier Part Number 1=S1011E-02-ND, Voltage_V=1.8kV
J9 J11: library part CMP-0054552-1, "Header, 100mil, 3x2, Tin, TH", Color=Black, Current_A=3A, Manufacturer="Sullins Connector Solutions", Supplier Part Number 1=S2012E-03-ND, Voltage_V=1.8kV
J10: library part CMP-0054542-1, "Header, 100mil, 4x2, Tin, TH", Color=Black, Current_A=3A, Manufacturer="Sullins Connector Solutions", Supplier Part Number 1=S2012E-04-ND, Voltage_V=1.8kV
J13: library part CMP-0002337-1, "Header, 100mil, 2x1, Tin, TH", Color=Black, Current_A=3A, Manufacturer="Sullins Connector Solutions", Supplier Part Number 1=S1012E-02-ND, Voltage_V=1.8kV
Logo1: library part CMP-0074844-1
Logo2: library part CMP-0074769-1
Logo4: library part CMP-0074847-1, "FCC_disclaimer"
Logo5: library part CMP-0074837-1, "IEC 61010-1 Hot Surface Warning"
NT1: library part CMP-0078142-3, "Single point connection between nets.", Manufacturer=N/A
Q1: library part CMP-0000586-2, "MOSFET, N-CH, 30 V, 100 A, DNK0008A (VSON-CLIP-8)", Manufacturer="Texas Instruments", Supplier Part Number 1=CSD17573Q5B-ND, Value1=0.0014, Value2="49 nC"
Q2: library part CMP-0000768-1, "MOSFET, N-CH, 60 V, 115 A, SOT-23", Manufacturer="Fairchild Semiconductor", Supplier Part Number 1=2N7002NCT-ND
Q3: library part CMP-0000711-1, "MOSFET, N-CH, 40 V, 100 A, DQJ0008A (VSONP-8)", Alternate Manufacturer=None, Manufacturer="Texas Instruments", Supplier Part Number 1=CSD18511Q5A-ND, Value1=0.003, Value2="63 nC"
R1 R14: library part CMP-0022899-2, "RES, 1.00 M, 1%, 0.1 W, 0603", Manufacturer="Yageo America", Power_W=100mW, Supplier Part Number 1=311-1.00MHRCT-ND, TempCo="200 ppm/C", Tolerance_%=1%, Value2=0.1W, Value_Code=1M00, ValueDisplayed=1.00M
R2: library part CMP-0022026-4, "RES, 124 k, 1%, 0.1 W, AEC-Q200 Grade 0, 0603", Manufacturer=Vishay-Dale, Power_W=100mW, Supplier Part Number 1=541-124KHCT-ND, TempCo="100 ppm/C", Tolerance_%=1%, Value2=0.1W, Value_Code=124k
R3: library part CMP-0023165-3, "RES, 511, 1%, 0.1 W, 0603", Manufacturer="Yageo America", Power_W=100mW, Supplier Part Number 1=311-511HRCT-ND, TempCo="200 ppm/C", Tolerance_%=1%, Value2=0.1W, Value_Code=511R, ValueDisplayed=511
R4 R21: library part CMP-0022895-3, "RES, 1.00 k, 1%, 0.1 W, 0603", Manufacturer="Yageo America", Power_W=100mW, Supplier Part Number 1=311-1.00KHRCT-ND, TempCo="200 ppm/C", Tolerance_%=1%, Value2=0.1W, Value_Code=1k00, ValueDisplayed=1.00k
R5: library part CMP-0021014-3, "RES, 1.13, 1%, 0.125 W, AEC-Q200 Grade 0, 0805", Manufacturer=Vishay-Dale, Power_W=125mW, Supplier Part Number 1=541-1.13CCCT-ND, TempCo="100 ppm/C", Tolerance_%=1%, Value2=0.125W, Value_Code=1R13, ValueDisplayed=1.13
R6: library part CMP-0023129-3, "RES, 470, 1%, 0.1 W, 0603", Manufacturer="Yageo America", Power_W=100mW, Supplier Part Number 1=311-470HRCT-ND, TempCo="200 ppm/C", Tolerance_%=1%, Value2=0.1W, Value_Code=470R, ValueDisplayed=470
R7: library part CMP-0023404-3, "RES, 10.0 k, 0.1%, 0.1 W, 0603", Manufacturer="Susumu Co Ltd", Power_W=100mW, Supplier Part Number 1=RG16P10.0KBCT-ND, TempCo="25 ppm/C", Tolerance_%=0.1%, Value2=0.1W, Value_Code=10k0, ValueDisplayed=10.0k
R8: library part CMP-0023270-5, "RES, 768, 1%, 0.1 W, 0603", Manufacturer=Yageo, Power_W=100mW, Supplier Part Number 1=311-768HRCT-ND, TempCo="100 ppm/C", Tolerance_%=1%, Value2=0.1W, Value_Code=768R, ValueDisplayed=768
R9: library part CMP-0023013-5, "RES, 300, 1%, 0.1 W, 0603", Manufacturer=Yageo, Power_W=100mW, Supplier Part Number 1=311-300HRCT-ND, TempCo="100 ppm/C", Tolerance_%=1%, Value2=0.1W, Value_Code=300R, ValueDisplayed=300
R10: library part CMP-0023294-5, "RES, 82.0, 1%, 0.1 W, 0603", Manufacturer=Yageo, Power_W=100mW, Supplier Part Number 1=311-82.0HRCT-ND, TempCo="100 ppm/C", Tolerance_%=1%, Value2=0.1W, Value_Code=82R0, ValueDisplayed=82.0
R11: library part CMP-0023264-5, "RES, 73.2, 1%, 0.1 W, 0603", Manufacturer=Yageo, Power_W=100mW, Supplier Part Number 1=311-73.2HRCT-ND, TempCo="100 ppm/C", Tolerance_%=1%, Value2=0.1W, Value_Code=73R2, ValueDisplayed=73.2
R12: library part CMP-0024310-2, "RES, 511, 0.1%, 0.1 W, 0603", Manufacturer="Yageo America", Power_W=100mW, TempCo="25 ppm/C", Tolerance_%=0.1%, Value2=0.1W, Value_Code=511R, ValueDisplayed=511
R15: library part CMP-0023326-5, "RES, 95.3 k, 1%, 0.1 W, 0603", Manufacturer=Yageo, Power_W=100mW, Supplier Part Number 1=311-95.3KHRCT-ND, TempCo="100 ppm/C", Tolerance_%=1%, Value2=0.1W, Value_Code=95k3, ValueDisplayed=95.3k
S1: library part CMP-0085606-1, "Switch, SPST-NO, 0.05 A, 12 VDC, SMT", CurrentRating_mA=50A, Manufacturer=Alps
SH-J1 SH-J2 SH-J3 SH-J4 SH-J5 SH-J6 SH-J7: library part CMP-0003623-1, "Shunt, 100mil, Gold plated, Black", Alternate Manufacturer=3M, Alternate PartNumber=969102-0000-DA, Manufacturer=Samtec, Supplier Part Number 1=SNT-100-BK-G-ND
TP1 TP2 TP6: library part CMP-0055147-1, "Test Point, Multipurpose, Red, TH", Color=Red, Manufacturer=Keystone, PartNumber=5010, Supplier Part Number 1=36-5010-ND
TP3 TP5 TP11 TP12 TP13 TP14 TP15 TP18 TP19: library part CMP-0055149-1, "Test Point, Multipurpose, White, TH", Color=White, Manufacturer=Keystone, PartNumber=5012, Supplier Part Number 1=36-5012-ND
TP4 TP16: library part CMP-0055150-1, "Test Point, Multipurpose, Orange, TH", Color=Orange, Manufacturer=Keystone, PartNumber=5013, Supplier Part Number 1=36-5013-ND
TP7 TP10 TP17: library part CMP-0055148-1, "Test Point, Multipurpose, Black, TH", Color=Black, Manufacturer=Keystone, PartNumber=5011, Supplier Part Number 1=36-5011-ND
TP8 TP9: library part CMP-0055153-1, "Test Point, Compact, SMT", Manufacturer=Keystone, PartNumber=5016, Supplier Part Number 1=36-5016TR-ND
U1: library part CMP-0001573-1, "TPS25983", Manufacturer="Texas Instruments", Operating Temperature Range=to
U2: library part CMP-0071020-1, "100 mA, Quasi Low-Dropout Linear Voltage Regulator, 3-pin SOT-23, Pb-Free", Manufacturer="Texas Instruments", PackageTopMarking=L0A*XTT, PowerWise=N
U3: library part CMP-0077834-1, "22-V Precision Surge Protection Clamp, DRV0006A (WSON-6)", Alternate Manufacturer="Texas Instruments"
ZZ1: library part CMP-0077236-1
ZZ2: library part CMP-0077237-1
ZZ3: library part CMP-0077238-1

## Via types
v1: diameter 0.61, hole 0.305, L1-Top Layer to L4-Bottom Layer, tented both sides, 249 vias
v2: diameter 0.864, hole 0.406, L1-Top Layer to L4-Bottom Layer, 12 vias
v3: diameter 0.5, hole 0.2, L1-Top Layer to L4-Bottom Layer, 11 vias
v4: diameter 0.66, hole 0.305, L1-Top Layer to L4-Bottom Layer, tented both sides, 8 vias

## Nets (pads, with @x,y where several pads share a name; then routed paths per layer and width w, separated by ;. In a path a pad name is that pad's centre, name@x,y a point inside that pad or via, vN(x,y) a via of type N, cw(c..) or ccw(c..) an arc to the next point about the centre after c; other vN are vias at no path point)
DVDT: C18.1 J12.2 J12.4 R5.1 TP14.1 U1.15 | length 46
  L1-Top Layer w0.203: U1.15@40.013,40.39 41.007,40.39 v4(41.303,40.687)
  L1-Top Layer w0.381: C18.1@41.326,37.617 v1(44.856,34.087) 46.05,32.893 R5.1@46.05,32.766
  L3-PWR/SIG w0.381: v4(41.303,40.687) 41.303,37.589 44.831,34.061 54.195,24.697 54.195,20.481 J12.2@56.642,18.034 J12.4@59.182,18.034 TP14.1@65.38,18.034
DVOUT: Q3.1 Q3.2 Q3.3 TP6.1 U1.17 U1.18 U1.19 U1.20 U1.21 U1.22 U1.23 U1.24
  other v1: 36.906,43.442 38.941,43.443 37.841,43.464 38.463,44.4 37.435,44.418 39.164,45.569
GND: C1.2 C2.2 C4.2 C5.2 C7.2 C8.2 C9.2 C10.2 C11.2 C12.2 C13.2 C14.2 C15.2 C17.2 C18.2 J4.1 J11.1 NT1.1 Q2.2 R2.1 R3.1 R8.1 R9.1 R10.1 R11.1 R12.2 R15.1 R21.1 S1.2 TP8.1 TP9.1 TP10.1 U1.4 U1.5 U1.14 U1.26 U2.3 | length 4.4
  L1-Top Layer w0.508: R15.1@32.603,46.02 v1(33.835,46.02) ; Q2.2@41.03,56.132 v1(41.03,57.079) v1@41.077,57.079
  L3-PWR/SIG w0.508: v3(37,39.715) v3(38.1,39.715) v3(39.2,39.715)
  other v1: 43.764,2.616 45.058,2.615 46.328,2.615 27.803,2.638 29.073,2.638 30.343,2.638 43.773,3.844 45.043,3.844 46.313,3.844 27.788,3.867 29.058,3.867 30.328,3.867 40.056,9.754 21.082,9.982 49.903,10.054 52.593,10.054 13.868,10.084 31.14,10.084 55.194,10.084 16.459,10.109 28.626,10.109 36.347,10.135 9.5,10.211 45.618,10.211 61.011,10.211 26.111,10.236 25.412,33.474 28.214,33.555 30.551,33.573 31.821,33.573 37.843,33.573 39.113,33.573 30.551,34.605 31.821,34.605 37.897,34.605 39.113,34.605 26.16,34.715 27.43,34.715 24.003,35.941 25.319,36.031 42.63,37.419 43.742,37.419 32.842,38.049 34.087,38.049 42.649,38.4 43.742,38.39 35.87,52.239 36.61,52.865 36.606,55.167 36.609,56.167
ILIM: J10.2 J10.4 J10.6 J10.8 R12.1 TP12.1 U1.8 | length 52
  L1-Top Layer w0.203: v4(36.172,36.893) 37.35,38.07 U1.8@37.35,38.727
  L1-Top Layer w0.305: R12.1@34.86,36.795 34.958,36.893 v4(36.172,36.893) v4@36.075,36.795
  L3-PWR/SIG w0.305: J10.2@19.864,17.874 J10.4@22.404,17.874 J10.6@24.944,17.874 J10.8@27.484,17.874 34.217,24.607 34.217,34.938 v4(36.172,36.893)
  L4-Bottom Layer w0.381: J10.2@19.864,17.874 18.115,16.125 18.115,10.284 TP12.1@24.909,3.49
IMON: J6.2 J6.4 TP15.1 U1.9 | length 40.5
  L1-Top Layer w0.203: v4(36.072,35.469) 37.85,37.246 U1.9@37.85,38.727
  L3-PWR/SIG w0.305: J6.2@32.469,17.612 J6.4@35.009,17.612 36.072,18.676 v4(36.072,35.469)
  L4-Bottom Layer w0.381: J6.2@32.469,17.612 31.115,16.258 31.115,12.493 33.488,10.12 TP15.1@33.488,3.49
ITIMER: J9.2 J9.4 J9.6 TP11.1 U1.7 | length 51.9
  L1-Top Layer w0.203: v4(36.246,37.864) 36.85,38.468 U1.7@36.85,38.727
  L3-PWR/SIG w0.305: J9.2@10.206,17.874 J9.4@12.746,17.874 J9.6@15.286,17.874 17.095,17.874 33.332,34.11 33.332,35.288 35.623,37.578 35.96,37.578 v4(36.246,37.864)
  L4-Bottom Layer w0.381: J9.6@15.286,17.874 17.048,16.112 17.048,12.391 15.352,10.695 TP11.1@15.352,3.49
LOAD_ON: Q1.4 R6.2 TP16.1 | length 10.8
  L1-Top Layer w0.508: R6.2@52.116,23.564 R6.2@52.226,23.454 56.591,23.454 TP16.1@56.632,23.495 Q1.4@62.865,23.495
NetC5_1: C5.1 J4.3 | length 3
  L1-Top Layer w0.508: J4.3@51.073,15.072 51.18,14.966 C5.1@51.18,12.108 C5.1@51.18,12.079
NetC7_1: C7.1 J7.3 U2.1 | length 4.9
  L1-Top Layer w0.635: U2.1@33.471,54.925 33.7,55.154 C7.1@33.7,56.839 33.7,59.478 J7.3@33.488,59.69
NetC9_1: C9.1 J11.5 | length 3.3
  L1-Top Layer w0.508: C9.1@44.272,12.108 J11.5@44.272,15.334 ; C9.1@44.41,12.079 C9.1@44.41,12.108
NetC10_1: C10.1 J11.3 | length 2.9
  L1-Top Layer w0.508: C10.1@41.732,12.232 J11.3@41.732,15.166
NetC11_1: C11.1 J9.1 | length 3.5
  L1-Top Layer w0.508: J9.1@10.206,15.334 10.206,13.776 10.795,13.187 C11.1@10.795,12.103
NetC12_1: C12.1 J9.3 | length 3.3
  L1-Top Layer w0.508: C12.1@12.509,12.079 C12.1@12.509,12.108 ; C12.1@12.685,12.108 12.685,14.752 12.509,14.928 J9.3@12.746,15.165
NetC13_1: C13.1 J9.5 | length 3.1
  L1-Top Layer w0.508: C13.1@15.286,12.076 C13.1@15.286,12.108 J9.5@15.286,15.165
NetC14_1: C14.1 J12.1 | length 3.5
  L1-Top Layer w0.508: C14.1@56.473,12.079 56.642,12.247 J12.1@56.642,15.494
NetC15_1: C15.1 J12.3 | length 3.4
  L1-Top Layer w0.508: C15.1@59.182,12.103 J12.3@59.182,15.494
NetC17_1: C17.1 R1.1 R2.2 S1.1 TP3.1 U1.6 | length 42.9
  L1-Top Layer w0.229: v4(35.261,38.379) 35.296,38.414 35.296,39.126 35.561,39.39 U1.6@36.187,39.39
  L1-Top Layer w0.381: v1(23.52,40.005) S1.1@23.52,41.114 ; C17.1@28.245,39.586 28.956,40.297 v1(28.956,40.97) 29.31,41.324 R1.1@31.625,41.324 ; R1.1@31.458,41.351 31.458,39.598 R2.2@31.471,39.586
  L3-PWR/SIG w0.508: TP3.1@3.647,41.46 5.102,40.005 v1(23.52,40.005) 27.991,40.005 v1(28.956,40.97) 28.99,41.004 32.635,41.004 v4(35.261,38.379)
NetD3_1: D3.1 R4.2 | length 2.1
  L1-Top Layer w0.508: R4.2@36.438,60.476 38.43,60.476 D3.1@38.531,60.375
NetD3_2: D3.2 Q2.3 | length 3.5
  L1-Top Layer w0.508: Q2.3@38.531,55.281 Q2.3@38.63,55.182 Q2.3@38.63,55.325 ; D3.2@38.531,58.275 38.63,58.175 Q2.3@38.63,55.325 ; Q2.3@38.773,55.182 Q2.3@38.63,55.325
NetJ6_1: J6.1 R3.2 | length 3
  L1-Top Layer w0.508: R3.2@32.364,12.079 R3.2@32.364,12.108 ; R3.2@32.469,12.108 J6.1@32.469,15.072
NetJ6_3: J6.3 R21.2 | length 3
  L1-Top Layer w0.381: R21.2@35.001,12.108 35.001,15.065 J6.3@35.009,15.072 ; R21.2@35.135,12.079 R21.2@35.135,12.108
NetJ7_1: J7.1 TP4.1 | length 9.6
  L1-Top Layer w0.508: J7.1@33.488,64.77 33.488,68.703 TP4.1@37.493,72.707
NetJ7_2: J7.2 R4.1 R7.2 | length 5.1
  L1-Top Layer w0.635: J7.2@33.488,62.23 33.643,62.076 R4.1@36.438,62.076 38.383,62.076 R7.2@38.478,61.981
